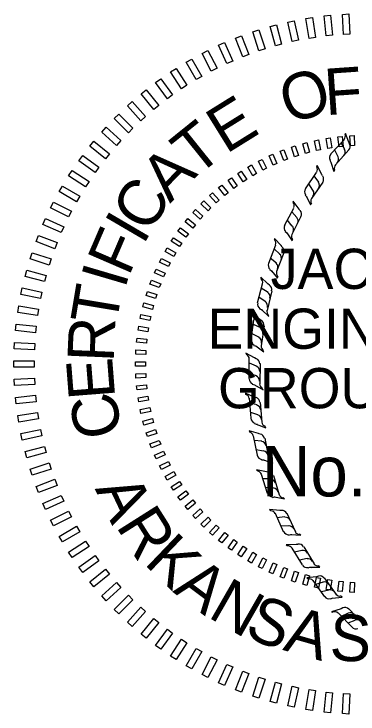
# Model space of a CAD drawing. Extents: x 1376650 to 1380188, y 377544 to 379765.
# Drawn here: x 1379812.9 to 1379910.8, y 377745.5 to 377944.5 of the extents above; entities that cross this region are included whole.
import ezdxf

# ---------------------------------------------------------------- set-up
doc = ezdxf.new("R2010")
doc.units = 0
doc.layers.add('Certificate of Authorization', color=7, linetype='Continuous')
doc.layers.add('R_Border PE', color=7, linetype='Continuous')

msp = doc.modelspace()

# ---------------------------------------------------------------- linework, layer by layer
at = {"layer": 'Certificate of Authorization'}
for points in [[(1379906.37, 377944.43), (1379908.21, 377944.53), (1379908.51, 377938.82), (1379906.67, 377938.72)], [(1379890.89, 377942.25), (1379892.7, 377942.63), (1379893.88, 377937.04), (1379892.08, 377936.66)], [(1379896.01, 377943.24), (1379897.83, 377943.53), (1379898.73, 377937.89), (1379896.91, 377937.6)], [(1379901.18, 377943.97), (1379903.01, 377944.17), (1379903.61, 377938.48), (1379901.77, 377938.29)], [(1379885.83, 377940.98), (1379887.61, 377941.46), (1379889.09, 377935.94), (1379887.31, 377935.46)], [(1379880.85, 377939.45), (1379882.6, 377940.02), (1379884.37, 377934.59), (1379882.61, 377934.02)], [(1379875.95, 377937.67), (1379877.67, 377938.33), (1379879.72, 377932.99), (1379878, 377932.33)], [(1379871.15, 377935.63), (1379872.83, 377936.38), (1379875.16, 377931.16), (1379873.47, 377930.41)], [(1379866.46, 377933.34), (1379868.1, 377934.18), (1379870.7, 377929.08), (1379869.06, 377928.25)], [(1379861.9, 377930.81), (1379863.5, 377931.73), (1379866.36, 377926.78), (1379864.76, 377925.86)], [(1379857.48, 377928.04), (1379859.03, 377929.05), (1379862.14, 377924.25), (1379860.59, 377923.25)], [(1379853.21, 377925.05), (1379854.7, 377926.13), (1379858.06, 377921.51), (1379856.57, 377920.43)], [(1379849.1, 377921.84), (1379850.53, 377923), (1379854.13, 377918.55), (1379852.7, 377917.39)], [(1379845.17, 377918.41), (1379846.54, 377919.65), (1379850.36, 377915.4), (1379848.99, 377914.17)], [(1379841.42, 377914.79), (1379842.72, 377916.09), (1379846.76, 377912.05), (1379845.46, 377910.75)], [(1379837.86, 377910.97), (1379839.1, 377912.34), (1379843.35, 377908.52), (1379842.11, 377907.15)], [(1379898.41, 377908.47), (1379899.57, 377908.71), (1379900.15, 377905.94), (1379899, 377905.69)], [(1379901.76, 377909.12), (1379902.92, 377909.3), (1379903.36, 377906.5), (1379902.2, 377906.32)], [(1379905.13, 377909.59), (1379906.3, 377909.72), (1379906.59, 377906.89), (1379905.42, 377906.77)], [(1379908.52, 377909.89), (1379909.69, 377909.95), (1379909.84, 377907.12), (1379908.66, 377907.06)], [(1379834.51, 377906.98), (1379835.67, 377908.41), (1379840.12, 377904.81), (1379838.96, 377903.38)], [(1379891.86, 377906.65), (1379892.98, 377907.01), (1379893.85, 377904.31), (1379892.73, 377903.95)], [(1379895.11, 377907.64), (1379896.25, 377907.95), (1379896.98, 377905.21), (1379895.85, 377904.9)], [(1379885.53, 377904.15), (1379886.6, 377904.63), (1379887.76, 377902.04), (1379886.68, 377901.56)], [(1379888.66, 377905.48), (1379889.76, 377905.9), (1379890.78, 377903.25), (1379889.68, 377902.83)], [(1379831.38, 377902.81), (1379832.46, 377904.3), (1379837.09, 377900.94), (1379836, 377899.45)], [(1379882.47, 377902.66), (1379883.52, 377903.19), (1379884.81, 377900.66), (1379883.76, 377900.13)], [(1379879.49, 377901.01), (1379880.51, 377901.6), (1379881.93, 377899.14), (1379880.91, 377898.55)], [(1379828.46, 377898.48), (1379829.47, 377900.03), (1379834.26, 377896.92), (1379833.26, 377895.37)], [(1379876.61, 377899.2), (1379877.59, 377899.84), (1379879.14, 377897.46), (1379878.15, 377896.82)], [(1379873.82, 377897.25), (1379874.77, 377897.94), (1379876.44, 377895.65), (1379875.49, 377894.95)], [(1379825.78, 377894.01), (1379826.7, 377895.61), (1379831.65, 377892.75), (1379830.73, 377891.15)], [(1379871.14, 377895.15), (1379872.05, 377895.89), (1379873.84, 377893.69), (1379872.92, 377892.95)], [(1379868.57, 377892.92), (1379869.45, 377893.71), (1379871.34, 377891.6), (1379870.47, 377890.81)], [(1379823.33, 377889.41), (1379824.17, 377891.05), (1379829.26, 377888.45), (1379828.43, 377886.81)], [(1379866.12, 377890.55), (1379866.96, 377891.39), (1379868.96, 377889.38), (1379868.13, 377888.55)], [(1379863.8, 377888.07), (1379864.59, 377888.94), (1379866.7, 377887.04), (1379865.91, 377886.17)], [(1379821.13, 377884.68), (1379821.88, 377886.36), (1379827.1, 377884.04), (1379826.35, 377882.35)], [(1379861.62, 377885.46), (1379862.36, 377886.37), (1379864.56, 377884.59), (1379863.82, 377883.67)], [(1379859.57, 377882.74), (1379860.26, 377883.69), (1379862.56, 377882.02), (1379861.86, 377881.07)], [(1379819.18, 377879.84), (1379819.84, 377881.56), (1379825.18, 377879.51), (1379824.52, 377877.79)], [(1379857.67, 377879.92), (1379858.31, 377880.9), (1379860.69, 377879.36), (1379860.05, 377878.37)], [(1379855.92, 377877), (1379856.5, 377878.02), (1379858.96, 377876.6), (1379858.37, 377875.58)], [(1379817.49, 377874.91), (1379818.06, 377876.66), (1379823.49, 377874.9), (1379822.92, 377873.14)], [(1379854.32, 377873.99), (1379854.85, 377875.04), (1379857.38, 377873.75), (1379856.85, 377872.71)], [(1379816.05, 377869.9), (1379816.53, 377871.68), (1379822.05, 377870.2), (1379821.57, 377868.42)], [(1379852.88, 377870.91), (1379853.36, 377871.98), (1379855.95, 377870.83), (1379855.47, 377869.75)], [(1379851.61, 377867.75), (1379852.03, 377868.85), (1379854.68, 377867.83), (1379854.26, 377866.74)], [(1379814.88, 377864.81), (1379815.26, 377866.62), (1379820.86, 377865.43), (1379820.47, 377863.63)], [(1379850.5, 377864.53), (1379850.86, 377865.65), (1379853.56, 377864.78), (1379853.2, 377863.66)], [(1379813.98, 377859.68), (1379814.27, 377861.5), (1379819.91, 377860.6), (1379819.62, 377858.78)], [(1379849.56, 377861.26), (1379849.87, 377862.4), (1379852.61, 377861.66), (1379852.3, 377860.53)], [(1379848.8, 377857.95), (1379849.04, 377859.1), (1379851.82, 377858.51), (1379851.57, 377857.36)], [(1379813.34, 377854.5), (1379813.54, 377856.33), (1379819.22, 377855.74), (1379819.03, 377853.9)], [(1379848.21, 377854.59), (1379848.39, 377855.75), (1379851.19, 377855.31), (1379851.01, 377854.15)], [(1379812.98, 377849.3), (1379813.08, 377851.14), (1379818.79, 377850.84), (1379818.69, 377849)], [(1379847.79, 377851.22), (1379847.92, 377852.38), (1379850.74, 377852.09), (1379850.62, 377850.92)], [(1379847.56, 377847.82), (1379847.62, 377848.99), (1379850.45, 377848.85), (1379850.39, 377847.67)], [(1379812.9, 377844.08), (1379812.9, 377845.93), (1379818.61, 377845.93), (1379818.61, 377844.08)], [(1379847.5, 377844.42), (1379847.5, 377845.59), (1379850.34, 377845.59), (1379850.34, 377844.42)], [(1379813.08, 377838.87), (1379812.98, 377840.71), (1379818.69, 377841.01), (1379818.79, 377839.17)], [(1379847.62, 377841.02), (1379847.56, 377842.19), (1379850.39, 377842.34), (1379850.45, 377841.16)], [(1379847.92, 377837.63), (1379847.79, 377838.8), (1379850.62, 377839.09), (1379850.74, 377837.92)], [(1379813.54, 377833.68), (1379813.34, 377835.51), (1379819.03, 377836.11), (1379819.22, 377834.27)], [(1379848.39, 377834.26), (1379848.21, 377835.42), (1379851.01, 377835.86), (1379851.19, 377834.7)], [(1379814.27, 377828.51), (1379813.98, 377830.33), (1379819.62, 377831.23), (1379819.91, 377829.41)], [(1379849.04, 377830.91), (1379848.8, 377832.07), (1379851.57, 377832.65), (1379851.82, 377831.5)], [(1379849.87, 377827.61), (1379849.56, 377828.75), (1379852.3, 377829.48), (1379852.61, 377828.35)], [(1379815.26, 377823.39), (1379814.88, 377825.2), (1379820.47, 377826.38), (1379820.86, 377824.58)], [(1379850.86, 377824.36), (1379850.5, 377825.48), (1379853.2, 377826.35), (1379853.56, 377825.23)], [(1379852.03, 377821.16), (1379851.61, 377822.26), (1379854.26, 377823.28), (1379854.68, 377822.18)], [(1379816.53, 377818.33), (1379816.05, 377820.11), (1379821.57, 377821.59), (1379822.05, 377819.81)], [(1379853.36, 377818.03), (1379852.88, 377819.1), (1379855.47, 377820.26), (1379855.95, 377819.18)], [(1379854.85, 377814.97), (1379854.32, 377816.02), (1379856.85, 377817.31), (1379857.38, 377816.26)], [(1379818.06, 377813.35), (1379817.49, 377815.1), (1379822.92, 377816.87), (1379823.49, 377815.11)], [(1379856.5, 377811.99), (1379855.92, 377813.01), (1379858.37, 377814.43), (1379858.96, 377813.41)], [(1379819.84, 377808.45), (1379819.18, 377810.17), (1379824.52, 377812.22), (1379825.18, 377810.5)], [(1379858.31, 377809.11), (1379857.67, 377810.09), (1379860.05, 377811.64), (1379860.69, 377810.65)], [(1379821.88, 377803.65), (1379821.13, 377805.33), (1379826.35, 377807.66), (1379827.1, 377805.97)], [(1379860.26, 377806.32), (1379859.57, 377807.27), (1379861.86, 377808.94), (1379862.56, 377807.99)], [(1379862.36, 377803.64), (1379861.62, 377804.55), (1379863.82, 377806.34), (1379864.56, 377805.42)], [(1379824.17, 377798.96), (1379823.33, 377800.6), (1379828.43, 377803.2), (1379829.26, 377801.56)], [(1379864.59, 377801.07), (1379863.8, 377801.95), (1379865.91, 377803.84), (1379866.7, 377802.97)], [(1379866.96, 377798.62), (1379866.12, 377799.46), (1379868.13, 377801.46), (1379868.96, 377800.63)], [(1379869.45, 377796.3), (1379868.57, 377797.09), (1379870.47, 377799.2), (1379871.34, 377798.41)], [(1379826.7, 377794.4), (1379825.78, 377796), (1379830.73, 377798.86), (1379831.65, 377797.26)], [(1379872.05, 377794.12), (1379871.14, 377794.86), (1379872.92, 377797.06), (1379873.84, 377796.32)], [(1379829.47, 377789.98), (1379828.46, 377791.53), (1379833.26, 377794.64), (1379834.26, 377793.09)], [(1379874.77, 377792.07), (1379873.82, 377792.76), (1379875.49, 377795.06), (1379876.44, 377794.36)], [(1379877.59, 377790.17), (1379876.61, 377790.81), (1379878.15, 377793.19), (1379879.14, 377792.55)], [(1379880.51, 377788.42), (1379879.49, 377789), (1379880.91, 377791.46), (1379881.93, 377790.87)], [(1379832.46, 377785.71), (1379831.38, 377787.2), (1379836, 377790.56), (1379837.09, 377789.07)], [(1379883.52, 377786.82), (1379882.47, 377787.35), (1379883.76, 377789.88), (1379884.81, 377789.35)], [(1379886.6, 377785.38), (1379885.53, 377785.86), (1379886.68, 377788.45), (1379887.76, 377787.97)], [(1379889.76, 377784.11), (1379888.66, 377784.53), (1379889.68, 377787.18), (1379890.78, 377786.76)], [(1379835.67, 377781.6), (1379834.51, 377783.03), (1379838.96, 377786.63), (1379840.12, 377785.2)], [(1379892.98, 377783), (1379891.86, 377783.36), (1379892.73, 377786.06), (1379893.85, 377785.7)], [(1379896.25, 377782.06), (1379895.11, 377782.37), (1379895.85, 377785.11), (1379896.98, 377784.8)], [(1379899.57, 377781.3), (1379898.41, 377781.54), (1379899, 377784.32), (1379900.15, 377784.07)], [(1379902.92, 377780.71), (1379901.76, 377780.89), (1379902.2, 377783.69), (1379903.36, 377783.51)], [(1379906.3, 377780.29), (1379905.13, 377780.42), (1379905.42, 377783.24), (1379906.59, 377783.12)], [(1379839.1, 377777.67), (1379837.86, 377779.04), (1379842.11, 377782.86), (1379843.35, 377781.49)], [(1379909.69, 377780.06), (1379908.52, 377780.12), (1379908.66, 377782.95), (1379909.84, 377782.89)], [(1379842.72, 377773.92), (1379841.42, 377775.22), (1379845.46, 377779.26), (1379846.76, 377777.96)], [(1379846.54, 377770.36), (1379845.17, 377771.6), (1379848.99, 377775.85), (1379850.36, 377774.61)], [(1379850.53, 377767.01), (1379849.1, 377768.17), (1379852.7, 377772.62), (1379854.13, 377771.46)], [(1379854.7, 377763.88), (1379853.21, 377764.96), (1379856.57, 377769.59), (1379858.06, 377768.5)], [(1379859.03, 377760.96), (1379857.48, 377761.97), (1379860.59, 377766.76), (1379862.14, 377765.76)], [(1379863.5, 377758.28), (1379861.9, 377759.2), (1379864.76, 377764.15), (1379866.36, 377763.23)], [(1379868.1, 377755.83), (1379866.46, 377756.67), (1379869.06, 377761.76), (1379870.7, 377760.93)], [(1379872.83, 377753.63), (1379871.15, 377754.38), (1379873.47, 377759.6), (1379875.16, 377758.85)], [(1379877.67, 377751.68), (1379875.95, 377752.34), (1379878, 377757.68), (1379879.72, 377757.02)], [(1379882.6, 377749.99), (1379880.85, 377750.56), (1379882.61, 377755.99), (1379884.37, 377755.42)], [(1379887.61, 377748.55), (1379885.83, 377749.03), (1379887.31, 377754.55), (1379889.09, 377754.07)], [(1379892.7, 377747.38), (1379890.89, 377747.76), (1379892.08, 377753.36), (1379893.88, 377752.97)], [(1379897.83, 377746.48), (1379896.01, 377746.77), (1379896.91, 377752.41), (1379898.73, 377752.12)], [(1379903.01, 377745.84), (1379901.18, 377746.04), (1379901.77, 377751.72), (1379903.61, 377751.53)], [(1379908.21, 377745.48), (1379906.37, 377745.58), (1379906.67, 377751.29), (1379908.51, 377751.19)]]:
    msp.add_lwpolyline(points, close=True, dxfattribs=at)
at = {"layer": 'R_Border PE'}
for p, q in [((1379903.11, 377904.72), (1379906.88, 377908.78)), ((1379907.27, 377910.57), (1379907.17, 377910.37)), ((1379908.26, 377908.09), (1379907.27, 377910.57)), ((1379907.07, 377906.01), (1379906.08, 377907.89)), ((1379908.46, 377907.59), (1379908.26, 377908.09)), ((1379905.19, 377903.92), (1379904.2, 377905.81)), ((1379908.26, 377905.91), (1379904.4, 377901.64)), ((1379902.81, 377902.93), (1379903.11, 377902.44)), ((1379899.24, 377901.44), (1379899.04, 377901.05)), ((1379900.53, 377898.87), (1379899.24, 377901.44)), ((1379903.11, 377902.44), (1379903.9, 377899.76)), ((1379903.11, 377902.44), (1379903.21, 377902.24)), ((1379895.87, 377894.8), (1379899.04, 377899.46)), ((1379900.73, 377898.47), (1379900.53, 377898.87)), ((1379903.9, 377899.76), (1379904.2, 377900.25)), ((1379900.83, 377896.68), (1379897.55, 377892.02)), ((1379899.63, 377896.68), (1379898.35, 377898.47)), ((1379897.95, 377894.4), (1379896.86, 377896.19)), ((1379895.77, 377893.01), (1379896.16, 377892.62)), ((1379894.08, 377889.05), (1379892.39, 377891.33)), ((1379892.39, 377891.33), (1379892.39, 377890.93)), ((1379896.16, 377892.62), (1379897.35, 377890.24)), ((1379896.16, 377892.62), (1379896.36, 377892.42)), ((1379897.35, 377890.24), (1379897.55, 377890.73)), ((1379889.91, 377884.38), (1379892.59, 377889.34)), ((1379894.28, 377888.65), (1379894.08, 377889.05)), ((1379893.39, 377886.66), (1379892, 377888.25)), ((1379894.58, 377886.96), (1379892, 377881.8)), ((1379892.1, 377884.19), (1379890.71, 377885.97)), ((1379890.11, 377882.7), (1379890.61, 377882.3)), ((1379890.61, 377882.3), (1379892.1, 377880.02)), ((1379890.61, 377882.3), (1379890.71, 377882.1)), ((1379885.45, 377873.67), (1379887.43, 377878.93)), ((1379888.92, 377878.73), (1379887.04, 377880.71)), ((1379887.04, 377880.71), (1379887.04, 377880.42)), ((1379889.22, 377878.33), (1379888.92, 377878.73)), ((1379892.1, 377880.02), (1379892.2, 377880.42)), ((1379888.62, 377876.25), (1379886.94, 377877.74)), ((1379887.63, 377873.67), (1379885.85, 377875.06)), ((1379889.72, 377876.65), (1379887.63, 377871.29)), ((1379885.75, 377871.89), (1379886.24, 377871.49)), ((1379886.24, 377871.49), (1379887.93, 377869.41)), ((1379886.24, 377871.49), (1379886.34, 377871.29)), ((1379885.15, 377867.82), (1379883.17, 377869.7)), ((1379883.17, 377869.7), (1379883.17, 377869.31)), ((1379887.93, 377869.41), (1379888.03, 377869.8)), ((1379882.18, 377862.36), (1379883.67, 377867.82)), ((1379885.65, 377867.42), (1379885.15, 377867.82)), ((1379885.25, 377865.34), (1379883.27, 377866.53)), ((1379886.34, 377865.83), (1379884.95, 377860.18)), ((1379884.56, 377862.66), (1379882.67, 377863.95)), ((1379882.87, 377857.7), (1379880.49, 377859.29)), ((1379880.49, 377859.29), (1379880.59, 377858.89)), ((1379882.77, 377860.68), (1379883.37, 377860.48)), ((1379883.37, 377860.48), (1379885.45, 377858.49)), ((1379883.37, 377860.48), (1379883.57, 377860.18)), ((1379885.45, 377858.49), (1379885.25, 377858.99)), ((1379880.39, 377851.95), (1379881.19, 377857.5)), ((1379883.27, 377857.4), (1379882.87, 377857.7)), ((1379883.17, 377855.32), (1379881.09, 377856.21)), ((1379884.16, 377855.82), (1379883.27, 377850.16)), ((1379882.77, 377852.54), (1379880.69, 377853.63)), ((1379881.19, 377850.26), (1379881.78, 377850.16)), ((1379881.78, 377850.16), (1379884.06, 377848.48)), ((1379881.78, 377850.16), (1379881.98, 377849.96)), ((1379884.06, 377848.48), (1379883.76, 377848.87)), ((1379881.38, 377846.79), (1379878.9, 377848.08)), ((1379878.9, 377848.08), (1379879.1, 377847.68)), ((1379879.8, 377840.84), (1379879.8, 377846.49)), ((1379881.98, 377844.41), (1379879.9, 377845.2)), ((1379881.88, 377846.49), (1379881.38, 377846.79)), ((1379882.97, 377845.1), (1379882.87, 377839.35)), ((1379881.98, 377841.63), (1379879.7, 377842.33)), ((1379880.69, 377839.25), (1379881.38, 377839.05)), ((1379881.38, 377839.05), (1379883.86, 377837.66)), ((1379881.38, 377839.05), (1379881.58, 377838.95)), ((1379883.86, 377837.66), (1379883.47, 377838.06)), ((1379881.28, 377835.58), (1379878.8, 377836.67)), ((1379878.8, 377836.67), (1379878.8, 377836.38)), ((1379880.39, 377829.63), (1379879.9, 377835.28)), ((1379881.78, 377835.38), (1379881.28, 377835.58)), ((1379882.08, 377833.4), (1379879.99, 377833.9)), ((1379882.97, 377834.09), (1379883.47, 377828.44)), ((1379882.28, 377830.52), (1379880.29, 377831.22)), ((1379881.38, 377828.04), (1379881.88, 377827.94)), ((1379881.88, 377827.94), (1379884.56, 377826.85)), ((1379881.88, 377827.94), (1379882.18, 377827.94)), ((1379884.56, 377826.85), (1379884.36, 377827.25)), ((1379882.47, 377825.27), (1379879.8, 377825.96)), ((1379879.8, 377825.96), (1379879.99, 377825.66)), ((1379882.87, 377825.07), (1379882.47, 377825.27)), ((1379882.18, 377819.12), (1379881.09, 377824.57)), ((1379883.47, 377823.08), (1379881.28, 377823.28)), ((1379884.26, 377823.88), (1379885.35, 377818.32)), ((1379883.96, 377820.21), (1379881.78, 377820.6)), ((1379883.37, 377817.73), (1379883.96, 377817.73)), ((1379883.96, 377817.73), (1379886.54, 377816.83)), ((1379883.96, 377817.73), (1379884.16, 377817.63)), ((1379886.54, 377816.83), (1379886.34, 377817.23)), ((1379884.76, 377814.35), (1379881.98, 377814.95)), ((1379881.98, 377814.95), (1379882.18, 377814.65)), ((1379885.05, 377808.2), (1379883.37, 377813.56)), ((1379885.25, 377814.26), (1379884.76, 377814.35)), ((1379886.74, 377813.26), (1379888.43, 377807.81)), ((1379886.05, 377812.37), (1379883.76, 377812.37)), ((1379886.94, 377809.69), (1379884.56, 377809.89)), ((1379886.44, 377807.01), (1379887.04, 377807.21)), ((1379887.04, 377807.21), (1379889.91, 377806.62)), ((1379887.04, 377807.21), (1379887.34, 377807.11)), ((1379889.91, 377806.62), (1379889.42, 377806.92)), ((1379888.53, 377803.34), (1379885.65, 377803.64)), ((1379885.65, 377803.64), (1379885.95, 377803.25)), ((1379889.02, 377803.34), (1379888.53, 377803.34)), ((1379889.62, 377797.29), (1379887.34, 377802.45)), ((1379890.01, 377801.56), (1379887.73, 377801.26)), ((1379890.61, 377802.55), (1379892.99, 377797.29)), ((1379891.2, 377798.98), (1379888.82, 377798.88)), ((1379891.01, 377796.3), (1379891.7, 377796.5)), ((1379891.7, 377796.5), (1379894.58, 377796.3)), ((1379891.7, 377796.5), (1379892, 377796.5)), ((1379894.58, 377796.3), (1379894.08, 377796.6)), ((1379893.19, 377793.72), (1379890.41, 377793.62)), ((1379890.41, 377793.62), (1379890.71, 377793.33)), ((1379893.68, 377793.72), (1379893.19, 377793.72)), ((1379895.07, 377787.87), (1379892.1, 377792.63)), ((1379894.87, 377791.94), (1379892.79, 377791.54)), ((1379895.37, 377793.03), (1379898.35, 377788.17)), ((1379896.36, 377789.66), (1379894.18, 377789.26)), ((1379896.66, 377787.08), (1379897.15, 377787.28)), ((1379897.15, 377787.28), (1379899.93, 377787.28)), ((1379897.15, 377787.28), (1379897.45, 377787.18)), ((1379899.93, 377787.28), (1379899.54, 377787.67)), ((1379899.04, 377784.5), (1379896.26, 377784.2)), ((1379896.26, 377784.2), (1379896.56, 377783.9)), ((1379901.42, 377778.84), (1379898.05, 377783.41)), ((1379899.54, 377784.7), (1379899.04, 377784.5)), ((1379901.22, 377784.2), (1379904.59, 377779.44)), ((1379900.92, 377783.01), (1379898.74, 377782.32)), ((1379902.51, 377780.73), (1379900.43, 377780.23)), ((1379903.11, 377778.25), (1379903.5, 377778.45)), ((1379903.5, 377778.45), (1379906.28, 377778.75)), ((1379903.5, 377778.45), (1379903.8, 377778.55)), ((1379906.28, 377778.75), (1379905.88, 377779.04)), ((1379906.08, 377775.37), (1379903.3, 377774.58)), ((1379906.48, 377775.67), (1379906.08, 377775.37)), ((1379908.26, 377775.37), (1379912.23, 377771.21)), ((1379903.3, 377774.58), (1379903.6, 377774.48)), ((1379909.16, 377770.21), (1379905.29, 377774.18)), ((1379908.07, 377774.18), (1379906.08, 377773.19)), ((1379909.95, 377772.1), (1379907.97, 377771.31))]:
    msp.add_line(p, q, dxfattribs=at)
for centre, start, end in [((1379905.69, 377909.8), 322.2653, 21.0531), ((1379907.06, 377906.89), 318.0045, 26.3785), ((1379904.25, 377903.64), 138.0045, 206.3785), ((1379905.64, 377905.29), 318.0045, 26.3785), ((1379903.79, 377903.25), 318.0045, 26.3785), ((1379897.75, 377900.29), 329.9636, 28.7515), ((1379905.62, 377900.72), 142.2653, 201.0531), ((1379898.3, 377895.81), 325.7028, 34.0768), ((1379899.5, 377897.58), 325.7028, 34.0768), ((1379897.15, 377893.99), 145.7028, 214.0768), ((1379896.74, 377893.55), 325.7028, 34.0768), ((1379891.13, 377890.06), 337.2243, 36.0121), ((1379898.9, 377891.28), 149.9636, 208.7515), ((1379892.24, 377885.69), 332.9635, 41.3375), ((1379893.21, 377887.6), 332.9635, 41.3375), ((1379891.33, 377883.73), 152.9635, 221.3375), ((1379890.98, 377883.25), 332.9635, 41.3375), ((1379893.4, 377881.27), 157.2243, 216.0121), ((1379885.9, 377879.34), 343.6465, 42.4343), ((1379888.23, 377877.13), 339.3857, 47.7597), ((1379887.49, 377875.13), 339.3857, 47.7597), ((1379886.8, 377873.08), 159.3857, 227.7597), ((1379886.51, 377872.55), 339.3857, 47.7597), ((1379889.14, 377870.86), 163.6465, 222.4343), ((1379882.16, 377868.1), 350.445, 49.2329), ((1379884.74, 377866.18), 346.1842, 54.5582), ((1379884.24, 377864.1), 346.1842, 54.5582), ((1379883.8, 377861.98), 166.1842, 234.5582), ((1379883.57, 377861.43), 346.1842, 54.5582), ((1379879.74, 377857.65), 356.646, 55.4338), ((1379886.38, 377860.06), 170.445, 229.2329), ((1379882.51, 377856.02), 352.3852, 60.7592), ((1379882.24, 377853.9), 352.3852, 60.7592), ((1379882.03, 377851.75), 172.3852, 240.7592), ((1379881.86, 377851.17), 352.3852, 60.7592), ((1379884.8, 377850.12), 176.646, 235.4338), ((1379878.34, 377846.33), 3.9474, 62.7352), ((1379881.3, 377845.06), 359.6866, 68.0606), ((1379881.3, 377842.92), 359.6866, 68.0606), ((1379881.27, 377840.17), 359.6866, 68.0606), ((1379881.37, 377840.76), 179.6866, 248.0606), ((1379884.32, 377839.5), 183.9474, 242.7352), ((1379878.32, 377834.94), 9.4933, 68.2812), ((1379881.39, 377833.97), 5.2325, 73.6065), ((1379881.59, 377831.84), 5.2325, 73.6065), ((1379881.87, 377829.7), 185.2325, 253.6065), ((1379881.83, 377829.1), 5.2325, 73.6065), ((1379884.94, 377828.72), 189.4933, 248.2812), ((1379879.54, 377824.19), 15.7912, 74.579), ((1379882.7, 377823.56), 11.5304, 79.9044), ((1379883.13, 377821.46), 11.5304, 79.9044), ((1379883.64, 377819.36), 191.5304, 259.9044), ((1379883.67, 377818.76), 11.5304, 79.9044), ((1379886.79, 377818.73), 195.7912, 254.579), ((1379881.97, 377813.06), 22.0938, 80.8817), ((1379885.17, 377812.78), 17.8331, 86.207), ((1379885.83, 377810.75), 17.8331, 86.207), ((1379886.67, 377808.12), 17.8331, 86.207), ((1379886.57, 377808.72), 197.8331, 266.207), ((1379889.78, 377808.44), 202.0938, 260.8817), ((1379885.94, 377801.73), 29.1451, 87.9329), ((1379889.15, 377801.85), 24.8843, 93.2583), ((1379890.06, 377799.91), 24.8843, 93.2583), ((1379891.04, 377797.99), 204.8843, 273.2583), ((1379891.21, 377797.41), 24.8843, 93.2583), ((1379894.25, 377798.1), 209.1451, 267.9329), ((1379890.83, 377791.74), 36.0034, 94.7913), ((1379894.01, 377792.24), 31.7427, 100.1166), ((1379895.14, 377790.43), 31.7427, 100.1166), ((1379896.58, 377788.08), 31.7427, 100.1166), ((1379896.35, 377788.63), 211.7427, 280.1166), ((1379899.53, 377789.13), 216.0034, 274.7913), ((1379896.83, 377782.42), 40.9505, 99.7383), ((1379899.96, 377783.19), 36.6897, 105.0637), ((1379901.24, 377781.48), 36.6897, 105.0637), ((1379902.88, 377779.26), 36.6897, 105.0637), ((1379905.72, 377780.56), 220.9505, 279.7383), ((1379902.59, 377779.79), 216.6897, 285.0637), ((1379907.11, 377774.22), 44.9655, 113.3394), ((1379904.13, 377773.01), 49.2262, 108.0141), ((1379908.63, 377772.71), 44.9655, 113.3394), ((1379910.57, 377770.75), 44.9655, 113.3394), ((1379910.21, 377771.24), 224.9655, 293.3394)]:
    msp.add_arc(centre, 1.54, start, end, dxfattribs=at)

# ---------------------------------------------------------------- texts
at = {"layer": 'Certificate of Authorization'}
for s, rotation, p in [('O', 17.9056, (1379891.12, 377913.09)), ('F', 3.9823, (1379901.66, 377915.73)), ('E', 31.8289, (1379873.25, 377904.58)), ('T', 38.7906, (1379864.74, 377897.98)), ('A', 45.7522, (1379857.31, 377890.55)), ('C', 59.6755, (1379851.56, 377881.8)), ('I', 59.6755, (1379849.64, 377878.57)), ('F', 66.6372, (1379845.56, 377869.69)), ('I', 73.5988, (1379844.48, 377866.1)), ('T', 80.5605, (1379841.97, 377855.55)), ('R', 87.5222, (1379841.25, 377845.36)), ('E', 94.4838, (1379841.73, 377835.41)), ('C', 101.4455, (1379843.89, 377825.22)), ('A', 295.3688, (1379835.85, 377809.52)), ('R', 302.3304, (1379841.73, 377798.97)), ('K', 316.2537, (1379849.64, 377788.3)), ('A', 323.2154, (1379857.91, 377780.27)), ('N', 330.177, (1379867.74, 377773.2)), ('S', 337.1387, (1379878.05, 377767.8)), ('A', 344.1003, (1379889.2, 377763.73)), ('S', 358.0236, (1379902.62, 377760.73))]:
    msp.add_text(s, height=13.19, rotation=rotation, dxfattribs=at).set_placement(p)
for s, height, p in [('JACOBS', 11.447, (1379885.96, 377866.34)), ('ENGINEERING', 11.4468, (1379867.98, 377849.32)), ('GROUP, INC.', 11.4468, (1379870.98, 377832.41)), ('No. 176', 14.307, (1379883.47, 377807.36))]:
    msp.add_text(s, height=height, dxfattribs=at).set_placement(p)

doc.saveas('drawing.dxf')
